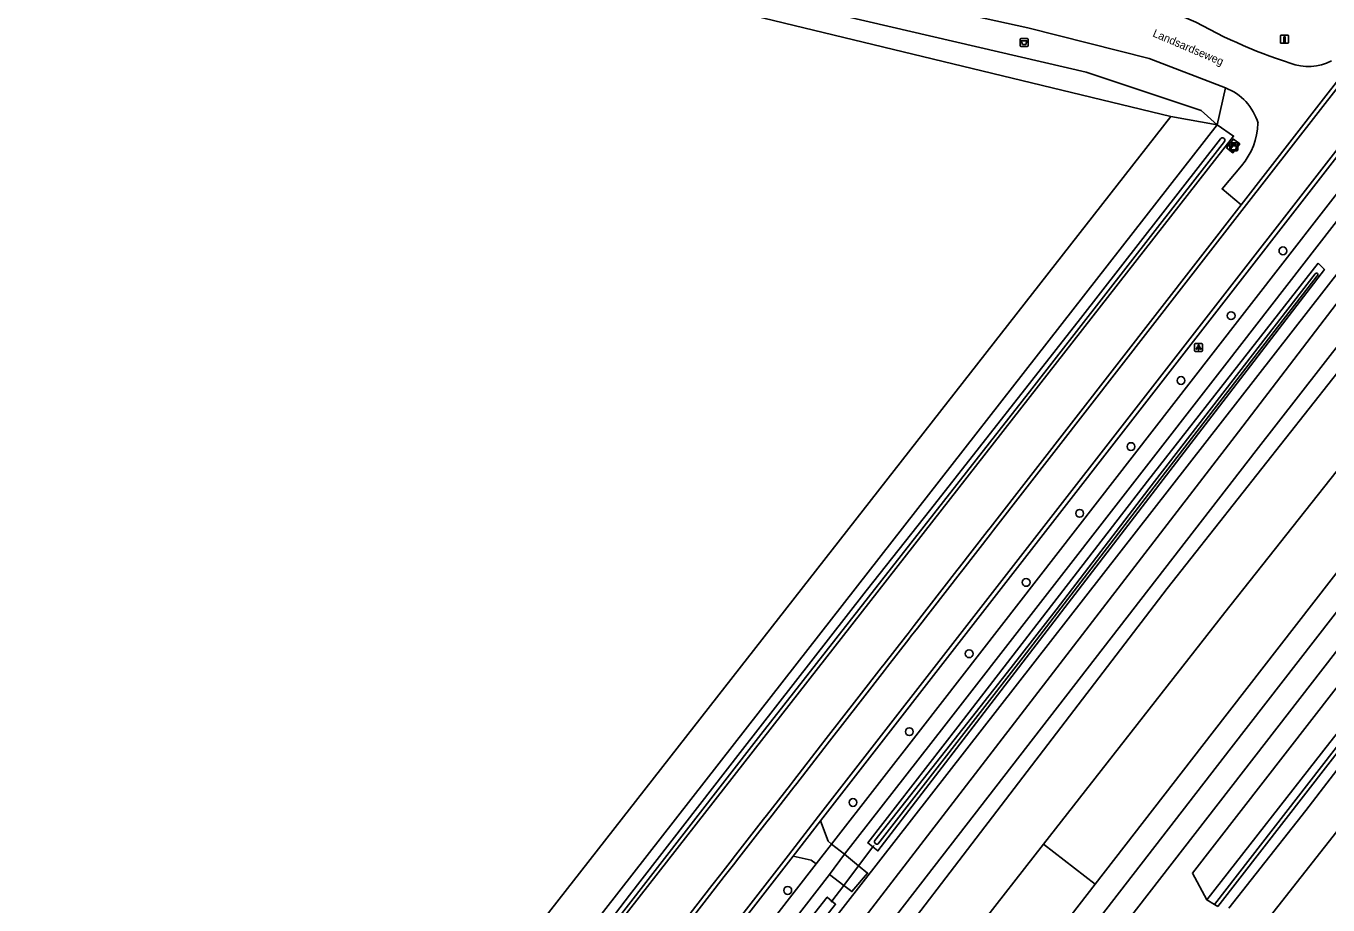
# Model space of a CAD drawing. Extents: x 152881 to 155736, y 382924 to 386919.
# Drawn here: x 154283.4 to 154446.1, y 385977.7 to 386087.5 of the extents above; entities that cross this region are included whole.
import ezdxf

# ---------------------------------------------------------------- set-up
doc = ezdxf.new("R2010")
doc.units = 0
for name, color, linetype in [('IMGEO_Afvalbak', 7, 'Continuous'), ('IMGEO_Berm_groen', 7, 'Continuous'), ('IMGEO_Boom', 7, 'Continuous'), ('IMGEO_Duiker', 7, 'Continuous'), ('IMGEO_Fietspad_gesloten', 7, 'Continuous'), ('IMGEO_Gemengd_bos', 7, 'Continuous'), ('IMGEO_Groenvoorziening', 7, 'Continuous'), ('IMGEO_Hek', 7, 'Continuous'), ('IMGEO_Kast', 7, 'Continuous'), ('IMGEO_Lichtpunt', 7, 'Continuous'), ('IMGEO_Openbare_ruimte_label', 7, 'Continuous'), ('IMGEO_Paal', 7, 'Continuous'), ('IMGEO_Rijbaan_lokaal_gesloten', 7, 'Continuous'), ('IMGEO_Rijbaan_lokaal_halfverhard', 7, 'Continuous'), ('IMGEO_Rijbaan_lokaal_open', 7, 'Continuous'), ('IMGEO_Waterloop', 7, 'Continuous')]:
    doc.layers.add(name, color=color, linetype=linetype)

msp = doc.modelspace()

# ---------------------------------------------------------------- linework, layer by layer
at = {"layer": 'IMGEO_Afvalbak'}
for p, q in [((154407.62, 386085.09), (154407.62, 386085.89)), ((154407.62, 386085.89), (154407.62, 386085.09)), ((154407.72, 386085.99), (154408.51, 386085.99)), ((154408.51, 386085.99), (154407.72, 386085.99)), ((154408.61, 386085.89), (154408.61, 386085.09)), ((154408.61, 386085.09), (154408.61, 386085.89)), ((154408.51, 386084.99), (154407.72, 386084.99)), ((154407.72, 386084.99), (154408.51, 386084.99))]:
    msp.add_line(p, q, dxfattribs=at)
msp.add_lwpolyline([(154407.76, 386085.71), (154408.46, 386085.71), (154408.31, 386085.24), (154407.91, 386085.24), (154407.76, 386085.71)], dxfattribs=at)
for centre, start, end in [((154407.72, 386085.89), 90, 180), ((154407.72, 386085.89), 90, 180), ((154408.51, 386085.89), 0, 90), ((154408.51, 386085.89), 360, 90), ((154407.72, 386085.09), 180, 270), ((154407.72, 386085.09), 180, 270), ((154408.51, 386085.09), 270, 0), ((154408.51, 386085.09), 270, 0)]:
    msp.add_arc(centre, 0.1, start, end, dxfattribs=at)
at = {"layer": 'IMGEO_Berm_groen'}
for points in [[(154283.85, 386110.7), (154284.89, 386114), (154347.24, 386097.73), (154415.86, 386081.79), (154430.22, 386077), (154432.23, 386075.19)], [(154206.41, 385715.95), (154210.92, 385723.91), (154254.97, 385801.6), (154261.48, 385812.76), (154268.29, 385823.71), (154276.29, 385835.8), (154284.64, 385847.62), (154293.34, 385859.19), (154359.89, 385944.57), (154465.13, 386079.58), (154471.19, 386087.08)], [(154432.23, 386075.19), (154433.26, 386079.82)], [(154318.21, 385929.07), (154317.62, 385928.31), (154319.46, 385926.75), (154343.37, 385957.43), (154376.62, 386000), (154434.28, 386073.8), (154432.23, 386075.19)], [(154433.42, 386072.32), (154434.27, 386073.42), (154435.06, 386072.81), (154434.21, 386071.7), (154433.42, 386072.32)], [(154444.87, 386057.93), (154423.54, 386030.66), (154399.81, 386000), (154388.59, 385985.49), (154389.2, 385984.99), (154389.83, 385984.49), (154401.74, 386000), (154445.63, 386057.11), (154444.87, 386057.93)], [(154384.09, 385978.22), (154383.51, 385978.72), (154373.63, 385966.16), (154374.62, 385965.16), (154384.54, 385977.82), (154384.09, 385978.22)]]:
    msp.add_lwpolyline(points, dxfattribs=at)
at = {"layer": 'IMGEO_Boom'}
for centre in [(154440.45, 386059.45), (154433.98, 386051.35), (154427.72, 386043.25), (154421.46, 386035), (154415.05, 386026.66), (154408.36, 386018.03), (154401.24, 386009.12), (154393.77, 385999.38), (154386.72, 385990.54), (154378.57, 385979.55)]:
    msp.add_circle(centre, 0.489, dxfattribs=at)
at = {"layer": 'IMGEO_Duiker'}
msp.add_lwpolyline([(154383.99, 385978.09), (154384.09, 385978.22), (154385.57, 385980.18), (154387.42, 385982.63), (154389.2, 385984.99), (154389.35, 385985.18)], dxfattribs=at)
at = {"layer": 'IMGEO_Fietspad_gesloten'}
for points in [[(154384.05, 385985.33), (154395.45, 386000), (154431.44, 386046.32), (154454.83, 386076.42)], [(154385.68, 385984.07), (154398.08, 386000), (154433.17, 386045.09), (154456.52, 386075.18)], [(154384.05, 385985.33), (154385.68, 385984.07)], [(154325.49, 385910.03), (154355.18, 385948.18), (154361.01, 385955.66), (154382.12, 385982.87)], [(154286.18, 385855.95), (154294.81, 385867.11), (154356.86, 385946.86), (154362.63, 385954.27), (154383.78, 385981.54)]]:
    msp.add_lwpolyline(points, dxfattribs=at)
at = {"layer": 'IMGEO_Gemengd_bos'}
for points in [[(154426.43, 386076.25), (154283.85, 386110.7)], [(154426.43, 386076.25), (154366.83, 386000), (154343.74, 385970.46), (154314.37, 385932.95), (154313.45, 385931.78)], [(154432.23, 386075.19), (154426.43, 386076.25)], [(154432.23, 386075.19), (154373.56, 386000), (154318.21, 385929.07)], [(154455.11, 386042.08), (154454.05, 386040.63), (154433.21, 386014.29), (154410.53, 385985.33)], [(154461.23, 386037.33), (154459.18, 386034.71), (154431.62, 385999.2), (154416.99, 385980.32)], [(154386.97, 385910.12), (154394.12, 385919.38), (154415.96, 385946.91), (154425.19, 385958.98), (154427.7, 385962.14), (154448.57, 385988.66), (154466.14, 386010.91), (154477.18, 386022.76), (154501.93, 385983.22), (154527.41, 385941.64), (154551.25, 385902.16)], [(154410.53, 385985.33), (154416.99, 385980.32)]]:
    msp.add_lwpolyline(points, dxfattribs=at)
at = {"layer": 'IMGEO_Groenvoorziening'}
for points in [[(154430.96, 385978.36), (154446.31, 385998.04), (154464.18, 386020.7), (154465.96, 386022.86), (154468.98, 386025.99), (154470.74, 386027.59), (154473.74, 386029.97), (154484.06, 386036.05), (154485.33, 386037.13), (154502.45, 386056.96), (154503.25, 386058.35), (154503.95, 386060.16), (154507.93, 386075.51), (154508.48, 386077.13), (154509.08, 386078.5), (154509.99, 386080.16), (154540.71, 386119.68), (154604.45, 386201.43)], [(154139.45, 385600.09), (154148.1, 385609.47), (154152.49, 385615.02), (154156.76, 385621.64), (154174.99, 385652.74), (154200.34, 385695.05), (154225.05, 385737.98), (154249.19, 385781.45), (154273.42, 385824.16), (154278.16, 385831.66), (154281.86, 385837.28), (154286.93, 385844.72), (154314.11, 385879.99), (154347.17, 385922.63), (154376.96, 385961.59), (154434.89, 386036.83), (154464.17, 386075.11), (154494.09, 386112.24), (154527.8, 386155.4), (154557.91, 386193.66)], [(154149.4, 385576.19), (154149.84, 385576.52), (154160.84, 385589.42), (154162.79, 385591.71), (154176.88, 385610.91), (154188.8, 385631.84), (154212.47, 385673.54), (154236.25, 385715.34), (154256.97, 385751.8), (154271.67, 385777.82), (154276.06, 385785.59), (154282.23, 385796.21), (154292.03, 385812.24), (154305.18, 385831.45), (154329.41, 385862.57), (154362.45, 385905.05), (154400.93, 385954.7), (154433.99, 385997.36), (154461.55, 386032.87), (154496.24, 386077.37), (154518.29, 386105.72), (154545.97, 386141.22), (154575.48, 386179.01)], [(154478.79, 386029.62), (154472.56, 386025.77), (154470.84, 386024.19), (154468.44, 386021.69), (154463.35, 386015.62), (154443.3, 385989.55), (154433.71, 385977.35)], [(154410.53, 385985.33), (154402.07, 385974.52), (154362.91, 385925.13), (154336.99, 385890.75), (154305.36, 385850.1), (154296.61, 385838.22), (154291.95, 385831.4), (154287.46, 385824.38), (154281.13, 385814.74), (154270.55, 385797.41), (154264.61, 385788.46), (154262.07, 385784.22), (154259.67, 385779.95), (154257.49, 385775.75), (154253.54, 385767.72), (154250.22, 385760.57)], [(154416.99, 385980.32), (154360.08, 385906.89), (154302.75, 385833.22), (154289.51, 385813.87), (154279.66, 385797.75), (154273.64, 385786.96), (154274.1, 385785.3), (154269.12, 385776.15), (154264.35, 385767.47), (154258.74, 385757.63), (154256.91, 385757.8), (154256.48, 385757.04)]]:
    msp.add_lwpolyline(points, dxfattribs=at)
at = {"layer": 'IMGEO_Hek'}
for points in [[(154616.72, 386229.45), (154606.39, 386218.56), (154575.48, 386179.01), (154545.97, 386141.22), (154518.29, 386105.72), (154496.24, 386077.37), (154461.55, 386032.87), (154433.99, 385997.36)], [(154433.99, 385997.36), (154400.93, 385954.7)]]:
    msp.add_lwpolyline(points, dxfattribs=at)
at = {"layer": 'IMGEO_Kast'}
for p, q in [((154433.81, 386072.04), (154433.81, 386072.88)), ((154433.81, 386072.88), (154433.81, 386072.04)), ((154433.88, 386072.96), (154434.72, 386072.96)), ((154434.72, 386072.96), (154433.88, 386072.96)), ((154434.81, 386072.89), (154434.81, 386072.05)), ((154434.81, 386072.05), (154434.81, 386072.89)), ((154434.73, 386071.96), (154433.89, 386071.96)), ((154433.89, 386071.96), (154434.73, 386071.96))]:
    msp.add_line(p, q, dxfattribs=at)
for points in [[(154434, 386072.75), (154434.6, 386072.75), (154434.6, 386072.67), (154434, 386072.67), (154434, 386072.75)], [(154434, 386072.58), (154434.6, 386072.58), (154434.6, 386072.09), (154434, 386072.09), (154434, 386072.58)]]:
    msp.add_lwpolyline(points, dxfattribs=at)
msp.add_circle((154434.09, 386072.43), 0.0377, dxfattribs=at)
for centre, start, end in [((154433.89, 386072.88), 92.4484, 184.2845), ((154433.89, 386072.88), 92.4484, 184.2845), ((154434.73, 386072.88), 2.4484, 94.2845), ((154434.73, 386072.88), 2.4484, 94.2845), ((154433.89, 386072.04), 182.4484, 274.2845), ((154433.89, 386072.04), 182.4484, 274.2845), ((154434.73, 386072.04), 272.4484, 4.2845), ((154434.73, 386072.04), 272.4484, 4.2845)]:
    msp.add_arc(centre, 0.0779, start, end, dxfattribs=at)
at = {"layer": 'IMGEO_Lichtpunt'}
for p, q in [((154429.41, 386047.78), (154429.41, 386046.98)), ((154429.41, 386047.78), (154429.41, 386046.98)), ((154430.31, 386047.88), (154429.51, 386047.88)), ((154430.31, 386047.88), (154429.51, 386047.88)), ((154429.51, 386046.88), (154430.31, 386046.88)), ((154429.51, 386046.88), (154430.31, 386046.88)), ((154430.41, 386046.98), (154430.41, 386047.78)), ((154430.41, 386046.98), (154430.41, 386047.78))]:
    msp.add_line(p, q, dxfattribs=at)
for points in [[(154429.79, 386047.45), (154429.83, 386047.42), (154429.64, 386047.16), (154429.6, 386047.18), (154429.79, 386047.45)], [(154429.89, 386047.4), (154429.94, 386047.4), (154429.94, 386047.08), (154429.89, 386047.08), (154429.89, 386047.4)], [(154430, 386047.42), (154430.04, 386047.45), (154430.22, 386047.18), (154430.19, 386047.16), (154430, 386047.42)]]:
    msp.add_lwpolyline(points, dxfattribs=at)
msp.add_circle((154429.91, 386047.58), 0.0994, dxfattribs=at)
for centre, start, end in [((154429.51, 386047.78), 90, 180), ((154429.51, 386047.78), 90, 180), ((154429.51, 386046.98), 180, 270), ((154429.51, 386046.98), 180, 270), ((154430.31, 386047.78), 0, 90), ((154430.31, 386047.78), 0, 90), ((154430.31, 386046.98), 270, 0), ((154430.31, 386046.98), 270, 360)]:
    msp.add_arc(centre, 0.0946, start, end, dxfattribs=at)
at = {"layer": 'IMGEO_Paal'}
for p, q in [((154440.14, 386086.31), (154440.14, 386085.47)), ((154440.14, 386086.31), (154440.14, 386085.47)), ((154441.06, 386086.39), (154440.22, 386086.39)), ((154441.06, 386086.39), (154440.22, 386086.39)), ((154440.23, 386085.4), (154441.07, 386085.4)), ((154440.23, 386085.4), (154441.07, 386085.4)), ((154441.14, 386085.48), (154441.14, 386086.32)), ((154441.14, 386085.48), (154441.14, 386086.32))]:
    msp.add_line(p, q, dxfattribs=at)
msp.add_lwpolyline([(154440.56, 386086.21), (154440.72, 386086.21), (154440.72, 386085.48), (154440.56, 386085.48), (154440.56, 386086.21)], dxfattribs=at)
for centre, start, end in [((154440.22, 386086.32), 92.4484, 184.2845), ((154440.22, 386086.32), 92.4484, 184.2845), ((154440.22, 386085.47), 182.4484, 274.2845), ((154440.22, 386085.47), 182.4484, 274.2845), ((154441.06, 386086.32), 2.4484, 94.2845), ((154441.06, 386086.32), 2.4484, 94.2845), ((154441.06, 386085.47), 272.4484, 4.2845), ((154441.06, 386085.47), 272.4484, 4.2845)]:
    msp.add_arc(centre, 0.0779, start, end, dxfattribs=at)
at = {"layer": 'IMGEO_Rijbaan_lokaal_gesloten'}
for points in [[(154328.78, 385919.82), (154378.66, 385983.96), (154382.43, 385988.81), (154449.38, 386074.91), (154451.4, 386077.51), (154455.3, 386082.52), (154459.68, 386088.15), (154463.2, 386092.67)], [(154435.22, 386065.19), (154445.23, 386078.07), (154450.52, 386084.87), (154454.11, 386089.48)], [(154450.73, 386084.29), (154435.62, 386064.85), (154404.27, 386024.54), (154403.91, 386024.07), (154400.45, 386019.61), (154400.11, 386019.18), (154394.77, 386012.31), (154394.4, 386011.84), (154394.01, 386011.34), (154393.7, 386010.93), (154391.03, 386007.51), (154390.67, 386007.04), (154387.92, 386003.5), (154387.63, 386003.13), (154383.8, 385998.21), (154383.08, 385997.28), (154379.69, 385992.92), (154379.31, 385992.43), (154376.32, 385988.59), (154375.97, 385988.13), (154372.47, 385983.64), (154371.79, 385982.75), (154370.64, 385981.27), (154369.51, 385979.83), (154362.66, 385971.01)], [(154452, 386077.4), (154449.8, 386074.57), (154382.65, 385988.23)], [(154435.22, 386065.19), (154403.86, 386024.86), (154403.5, 386024.4), (154400.03, 386019.94), (154399.7, 386019.5), (154394.35, 386012.63), (154393.99, 386012.16), (154393.6, 386011.66), (154393.28, 386011.25), (154390.62, 386007.83), (154390.25, 386007.36), (154387.51, 386003.83), (154387.21, 386003.45), (154383.39, 385998.53), (154382.67, 385997.6), (154379.28, 385993.25), (154378.9, 385992.76), (154375.91, 385988.91), (154375.55, 385988.45), (154372.06, 385983.96), (154371.37, 385983.08), (154370.22, 385981.59), (154369.1, 385980.15), (154362.24, 385971.33)], [(154382.65, 385988.23), (154379.23, 385983.84)], [(154379.23, 385983.84), (154329.19, 385919.5)]]:
    msp.add_lwpolyline(points, dxfattribs=at)
at = {"layer": 'IMGEO_Rijbaan_lokaal_halfverhard'}
for points in [[(154430.96, 385978.36), (154430.95, 385978.37), (154429.15, 385981.71), (154473.29, 386038.55), (154475.58, 386041.51), (154505.26, 386079.73), (154536.61, 386120.08), (154569.38, 386162.41), (154601.67, 386203.48), (154610.01, 386213.94), (154618.71, 386223.88), (154639.04, 386245.8), (154675.79, 386284), (154711.41, 386321.49), (154746.53, 386357.84), (154782.3, 386395.2), (154818.2, 386432.43)], [(154596.58, 386201.54), (154574.17, 386172.79), (154543.98, 386134.14), (154511.74, 386092.39), (154480.83, 386052.5), (154448.31, 386010.94), (154417.97, 385971.85), (154403.26, 385952.9), (154364.78, 385903.24)], [(154274.93, 386112.85), (154279.53, 386118.71), (154347.48, 386100.73), (154408.56, 386087.31), (154423.72, 386083.48), (154433.26, 386079.82)], [(154425.85, 386089.6), (154429.57, 386088.04), (154433.08, 386086.21), (154433.88, 386085.83), (154434.68, 386085.47), (154435.49, 386085.11), (154437.13, 386084.42), (154437.96, 386084.09), (154438.8, 386083.78), (154439.64, 386083.47), (154440.63, 386083.14), (154441.37, 386082.91)], [(154435.28, 386070.08), (154432.85, 386067.18), (154435.22, 386065.19)], [(154431.9, 385977.79), (154430.96, 385978.36)], [(154432.3, 385977.54), (154431.9, 385977.79)]]:
    msp.add_lwpolyline(points, dxfattribs=at)
for centre, radius, start, end in [((154443.65, 386088.87), 6.38, 248.9934, 296.7735), ((154430.93, 386073.58), 6.66, 15.7866, 69.5278), ((154428.69, 386075.68), 8.65, 319.6578, 358.1243)]:
    msp.add_arc(centre, radius, start, end, dxfattribs=at)
at = {"layer": 'IMGEO_Rijbaan_lokaal_open'}
for points in [[(154382.65, 385988.23), (154383.61, 385985.72), (154384.05, 385985.33)], [(154382.12, 385982.87), (154384.05, 385985.33)], [(154382.12, 385982.87), (154381.51, 385983.35), (154379.23, 385983.84)], [(154385.68, 385984.07), (154383.78, 385981.54)], [(154383.78, 385981.54), (154385.57, 385980.18), (154386.59, 385979.41), (154388.54, 385981.71), (154387.42, 385982.63), (154385.68, 385984.07)]]:
    msp.add_lwpolyline(points, dxfattribs=at)
at = {"layer": 'IMGEO_Waterloop'}
for points in [[(154432.3, 385977.54), (154462.58, 386016.47), (154468.45, 386023.22), (154470.99, 386025.72), (154473.53, 386027.86), (154484.23, 386034.17), (154485.44, 386035.11), (154486.61, 386036.27), (154503.19, 386055.31), (154504.33, 386057.05), (154505.09, 386058.68), (154505.37, 386059.45), (154509.28, 386074.93), (154510.04, 386076.9), (154510.88, 386078.57), (154512.29, 386080.72), (154610.52, 386206.7)], [(154598.48, 386192.19), (154541.78, 386119.39), (154511.08, 386079.78), (154510.35, 386078.65), (154509.49, 386076.95), (154508.84, 386075.07), (154504.68, 386058.9), (154504.24, 386057.83), (154503.22, 386056.11), (154487.17, 386037.54), (154485.67, 386035.93), (154484.38, 386034.85), (154475.66, 386029.84), (154472.71, 386027.81), (154470.75, 386026.13), (154466, 386021.27), (154448.15, 385998.73), (154431.9, 385977.79)], [(154317.94, 385880.84), (154349.2, 385920.97), (154437.1, 386034.51), (154466.95, 386072.77), (154496.38, 386110.01), (154559.32, 386190.77)], [(154560.71, 386188.88), (154496.93, 386107.91), (154466.19, 386069.25), (154449.63, 386047.24), (154425.99, 386017.26), (154367.53, 385940.89), (154334.81, 385897.94)], [(154319.91, 385928.87), (154326.08, 385936.6), (154342.37, 385957.74), (154350.71, 385968.38), (154358.79, 385978.97), (154372.64, 385996.77), (154388.37, 386016.99), (154396.46, 386027.19), (154415.15, 386051.01), (154432.64, 386073.46)], [(154433.13, 386073.12), (154409.08, 386042.21), (154375.19, 385999.01), (154353.31, 385970.84), (154343.04, 385957.69), (154320.32, 385928.59)], [(154389.45, 385985.78), (154406.47, 386007.42), (154412.1, 386014.61), (154423.69, 386029.73), (154444.47, 386056.6)], [(154444.75, 386056.32), (154423.25, 386028.52), (154407.98, 386008.68), (154389.83, 385985.35)]]:
    msp.add_lwpolyline(points, dxfattribs=at)
for centre, radius, start, end in [((154432.88, 386073.28), 0.297, 327.5749, 142.4727), ((154444.63, 386056.47), 0.203, 308.4122, 139.7817), ((154389.72, 385985.63), 0.302, 150.236, 291.6636)]:
    msp.add_arc(centre, radius, start, end, dxfattribs=at)

# ---------------------------------------------------------------- texts
at = {"layer": 'IMGEO_Openbare_ruimte_label'}
msp.add_text('Landsardseweg', height=1, rotation=336.9969, dxfattribs=at).set_placement((154424.09, 386086.27))

doc.saveas('drawing.dxf')
